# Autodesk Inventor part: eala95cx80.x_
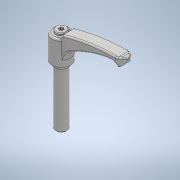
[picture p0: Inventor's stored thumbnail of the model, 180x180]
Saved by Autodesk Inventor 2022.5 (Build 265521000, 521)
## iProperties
Created: 2018-05
Part Number: eala95cx80.x_
Material: 一般
Document SubType Name: Modeling
Designer: imaocorp
Density: 1 g/cm^3
Appearance: 既定
Sending System: SOLIDWORKS 2016-2016286
MC: AMD64
MC_MODEL: AMD64 Family 21 Model 2 Stepping 0, AuthenticAMD
OS: Windows_NT
FRU: Parasolid Version 28.0, build 224,  7-29-2016
FORMAT: text
GUISE: transmit
KEY: eala95cx80
FILE: eala95cx80.x_t
DATE: Fri May 18 11:34:30 2018
Author: imaocorp
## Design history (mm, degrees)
feature "Base1"
node "ソリッド1"
